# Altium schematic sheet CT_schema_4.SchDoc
size 574 x 363 mm
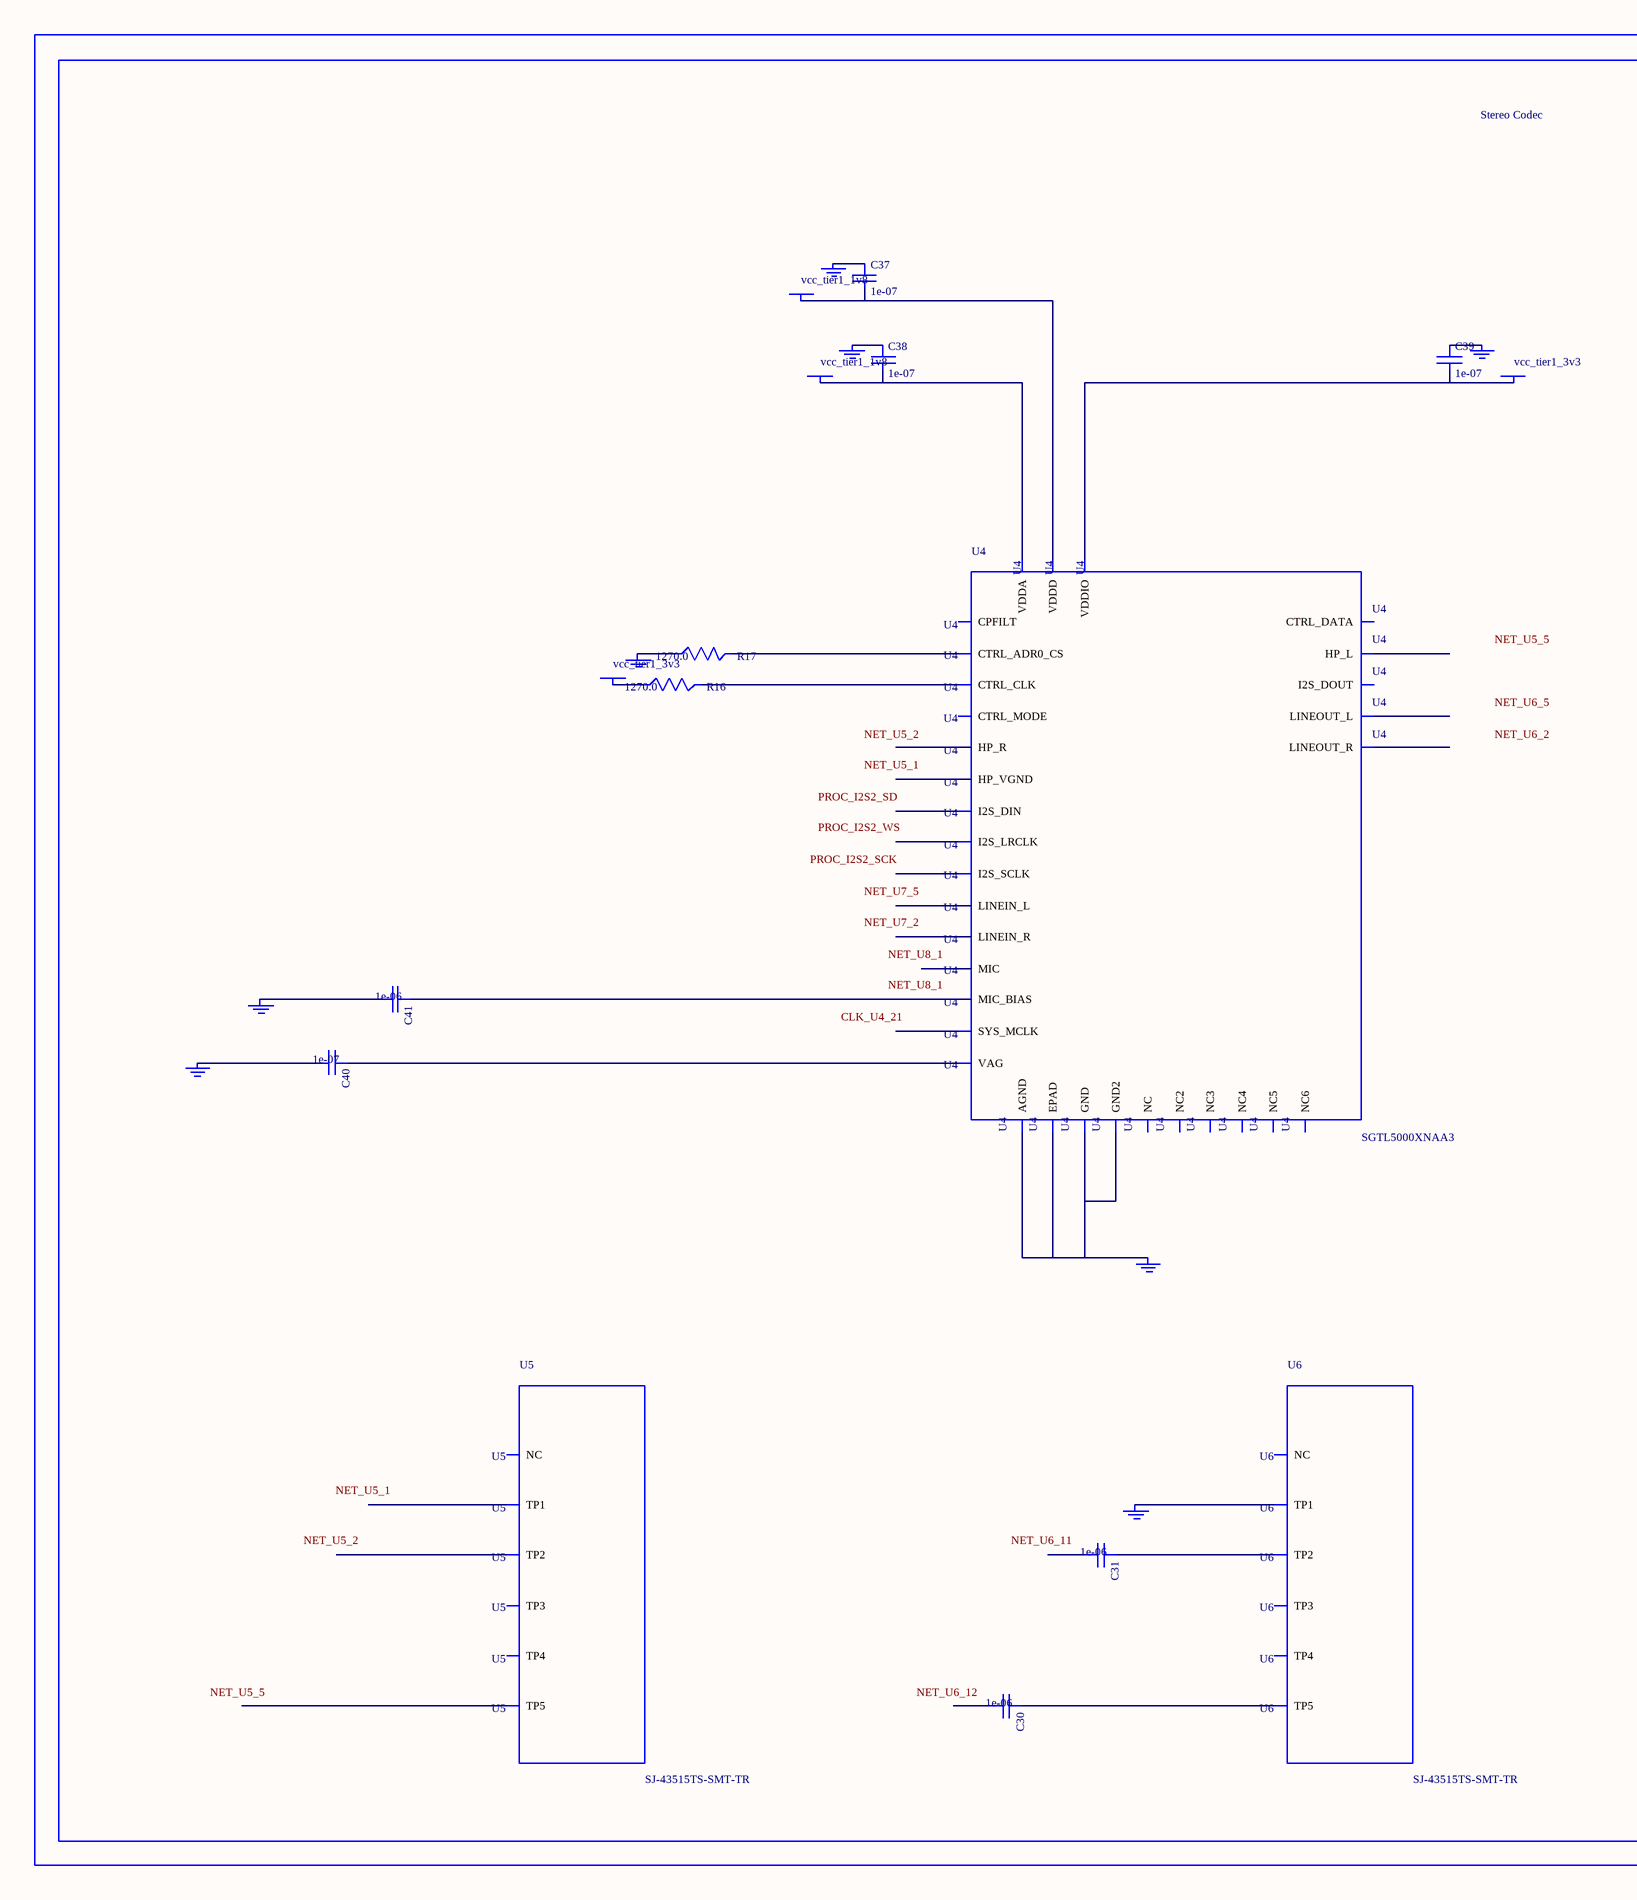
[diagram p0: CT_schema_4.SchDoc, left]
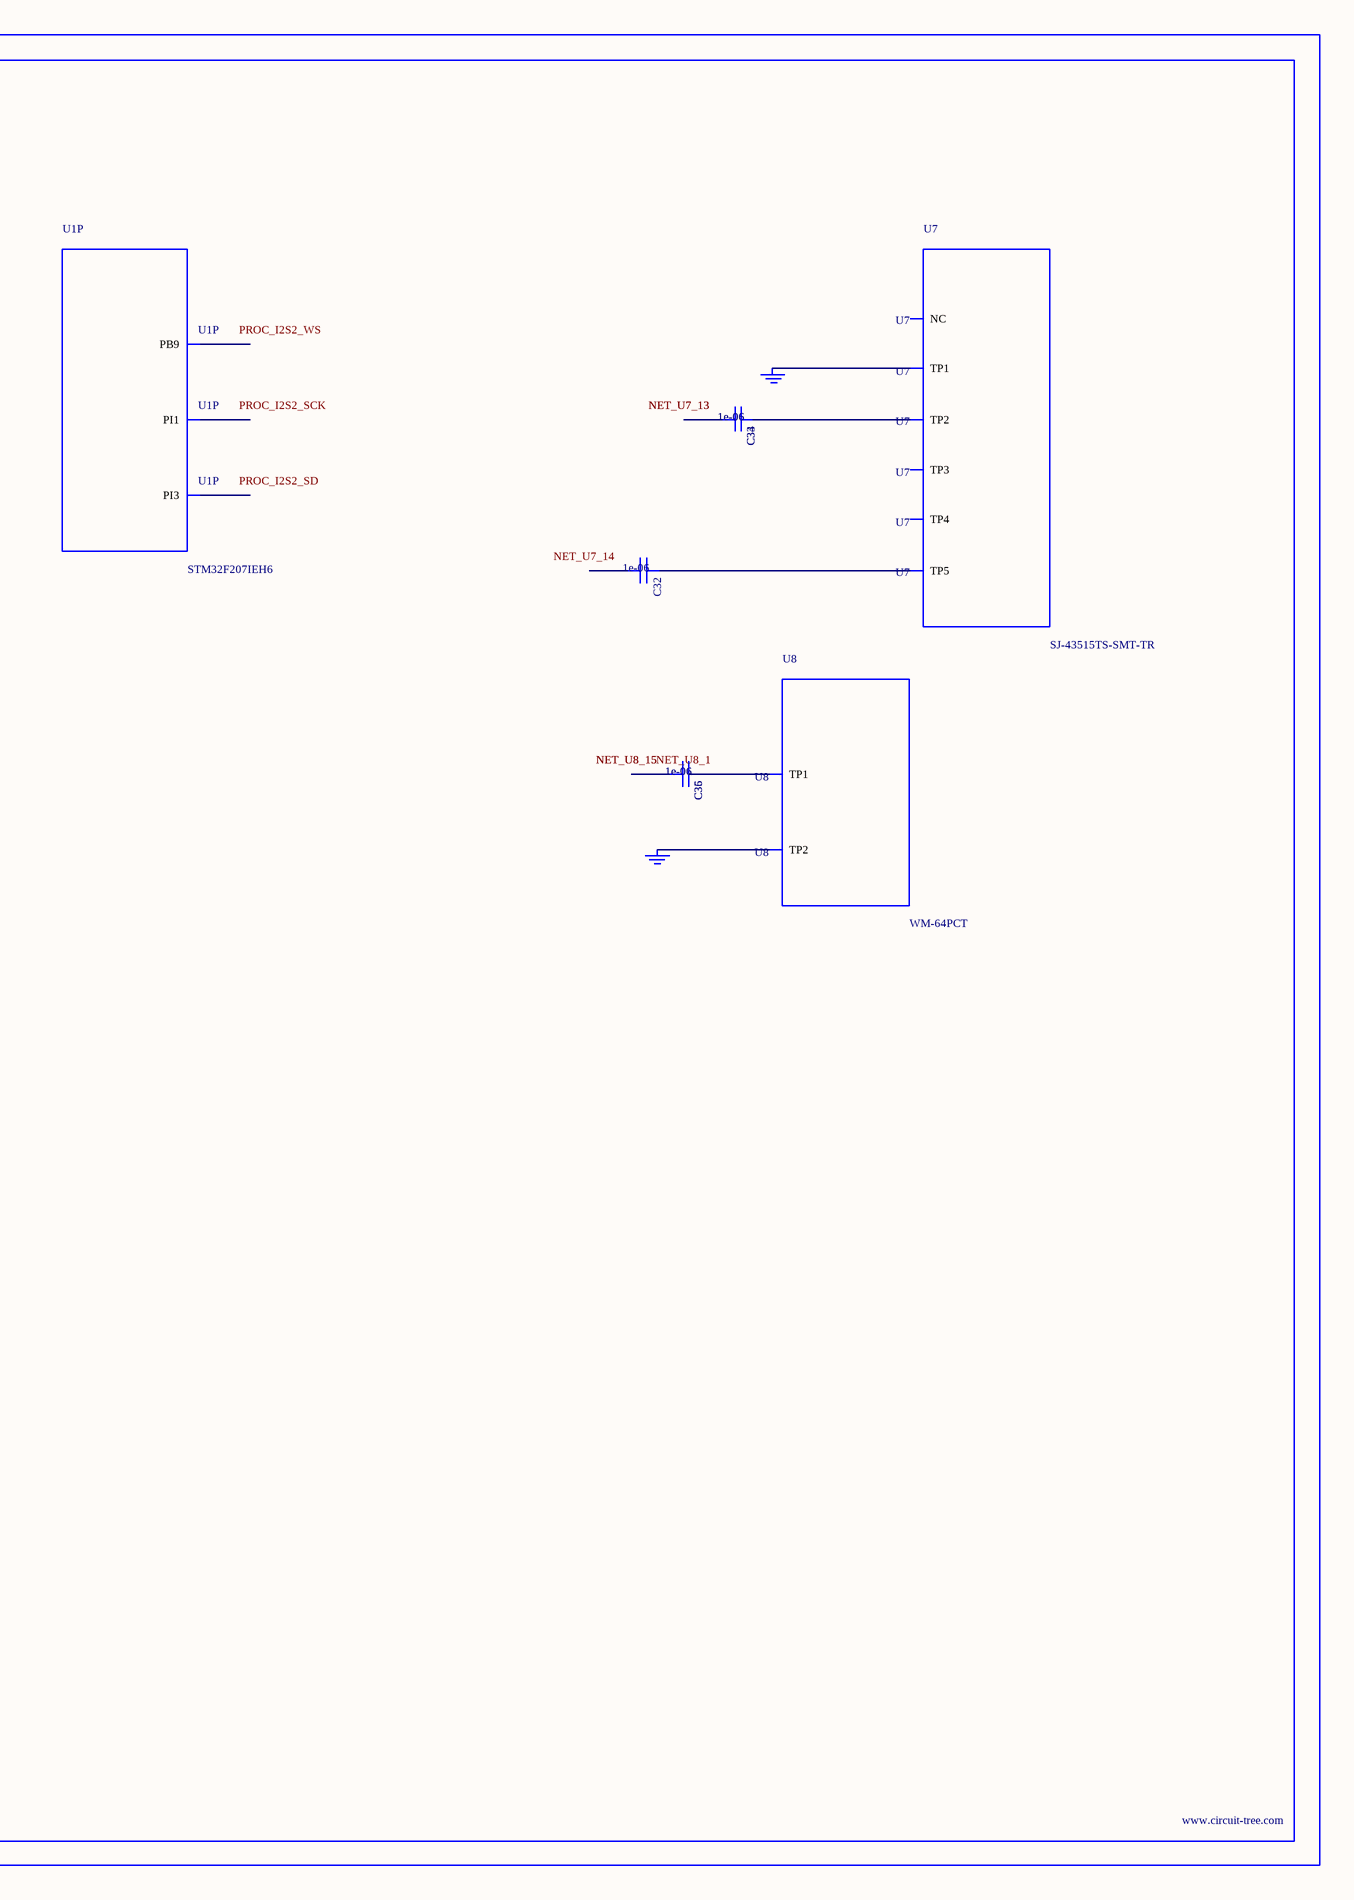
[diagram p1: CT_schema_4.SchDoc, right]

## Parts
BORDER3  (no value)
C30  1e-06  [C0603]
C31  1e-06  [C0603]
C32  1e-06  [C0603]
C33  1e-06  [C0603]
C34  1e-06  [C0603]
C35  1e-06  [C0603]
C36  1e-06  [C0603]
C37  1e-07  [C0402]
C38  1e-07  [C0402]
C39  1e-07  [C0402]
C40  1e-07  [C0402]
C41  1e-06  [C0603]
GND_INSTANCE_3_0  (no value)
GND_INSTANCE_3_1  (no value)
GND_INSTANCE_3_2  (no value)
GND_INSTANCE_3_3  (no value)
GND_INSTANCE_3_4  (no value)
GND_INSTANCE_3_5  (no value)
GND_INSTANCE_3_6  (no value)
GND_INSTANCE_3_7  (no value)
GND_INSTANCE_3_8  (no value)
GND_INSTANCE_3_9  (no value)
GND_INSTANCE_3_10  (no value)
POWER_INSTANCE_3_0  vcc_tier1_1v8
POWER_INSTANCE_3_1  vcc_tier1_3v3
POWER_INSTANCE_3_2  vcc_tier1_3v3
POWER_INSTANCE_3_3  vcc_tier1_1v8
R16  1270.0  [R0603]
R17  1270.0  [R0603]
U1  STM32F207IEH6  [UFBGA176_25]  (part P of 18)
U4  SGTL5000XNAA3  [QFN-32]
U5  SJ-43515TS-SMT-TR  [SJ-43515TS-SMT-TR]
U6  SJ-43515TS-SMT-TR  [SJ-43515TS-SMT-TR]
U7  SJ-43515TS-SMT-TR  [SJ-43515TS-SMT-TR]
U8  WM-64PCT  [WM-64PC]

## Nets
NetC30_1: C30.1 U6.5(TP5)
NetC31_1: C31.1 U6.2(TP2)
NetC32_1: C32.1 U7.5(TP5)
NetC33_1: C33.1 C34.1 U7.2(TP2)
NetC33_2: C33.2 C34.2
NetC35_1: C35.1 C36.1 U8.1(TP1)
NetC35_2: C35.2 C36.2
NetC37_1: C37.1 GND_INSTANCE_3_5.0(GND)
NetC37_2: C37.2 POWER_INSTANCE_3_3.0(PWR) U4.30(VDDD)
NetC38_1: C38.1 GND_INSTANCE_3_1.0(GND)
NetC38_2: C38.2 POWER_INSTANCE_3_0.0(PWR) U4.5(VDDA)
NetC39_1: C39.1 GND_INSTANCE_3_4.0(GND)
NetC39_2: C39.2 POWER_INSTANCE_3_1.0(PWR) U4.20(VDDIO)
NetC40_1: C40.1 U4.10(VAG)
NetC40_2: C40.2 GND_INSTANCE_3_2.0(GND)
NetC41_1: C41.1 U4.16(MIC_BIAS)
NetC41_2: C41.2 GND_INSTANCE_3_3.0(GND)
NetGND_INSTANCE_3_0_0: GND_INSTANCE_3_0.0(GND) U4.1(GND) U4.3(GND2) U4.7(AGND) U4.EXP(EPAD)
NetGND_INSTANCE_3_6_0: GND_INSTANCE_3_6.0(GND) R17.1
NetGND_INSTANCE_3_7_0: GND_INSTANCE_3_7.0(GND) U6.1(TP1)
NetGND_INSTANCE_3_8_0: GND_INSTANCE_3_8.0(GND) GND_INSTANCE_3_9.0(GND) U7.1(TP1)
NetGND_INSTANCE_3_10_0: GND_INSTANCE_3_10.0(GND) U8.2(TP2)
NetPOWER_INSTANCE_3_2_0: POWER_INSTANCE_3_2.0(PWR) R16.1
NetR16_2: R16.2 U4.29(CTRL_CLK)
NetR17_2: R17.2 U4.31(CTRL_ADR0_CS)

Not connected (* = marked no-connect by the designer): C30 2; C31 2; C32 2; U1 B4(PB9) C13(PI3) D14(PI1); U4 2(HP_R) 4(HP_VGND) 6(HP_L) 8(NC) 9(NC2) 11(LINEOUT_R) 12(LINEOUT_L) 13(LINEIN_R) 14(LINEIN_L) 15(MIC) 17(NC3) 18(CPFILT) 19(NC4) 21(SYS_MCLK) 22(NC5) 23(I2S_LRCLK) 24(I2S_SCLK) 25(I2S_DOUT) 26(I2S_DIN) 27(CTRL_DATA) 28(NC6) 32(CTRL_MODE); U5 1(TP1) 2(TP2) 3(TP3) 4(TP4) 5(TP5) 6(NC); U6 3(TP3) 4(TP4) 6(NC); U7 3(TP3) 4(TP4) 6(NC)

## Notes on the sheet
- Labels drawn without touching a wire or pin: CLK_U4_21, NET_U5_1, NET_U5_2, NET_U5_5, NET_U6_2, NET_U6_5, NET_U6_11, NET_U6_12, NET_U7_2, NET_U7_5, NET_U7_14, NET_U8_1, PROC_I2S2_SCK, PROC_I2S2_SD, PROC_I2S2_WS

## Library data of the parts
BORDER3 = BORDER_PAGE3
C30-C36 C41 = C0603C105K3RACTU
C37-C40 = C0402C104K3RACTU
GND_INSTANCE_3_0-GND_INSTANCE_3_10 = GND
POWER_INSTANCE_3_0-POWER_INSTANCE_3_3 = PWR
R16 R17 = RC0603FR-071K27L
